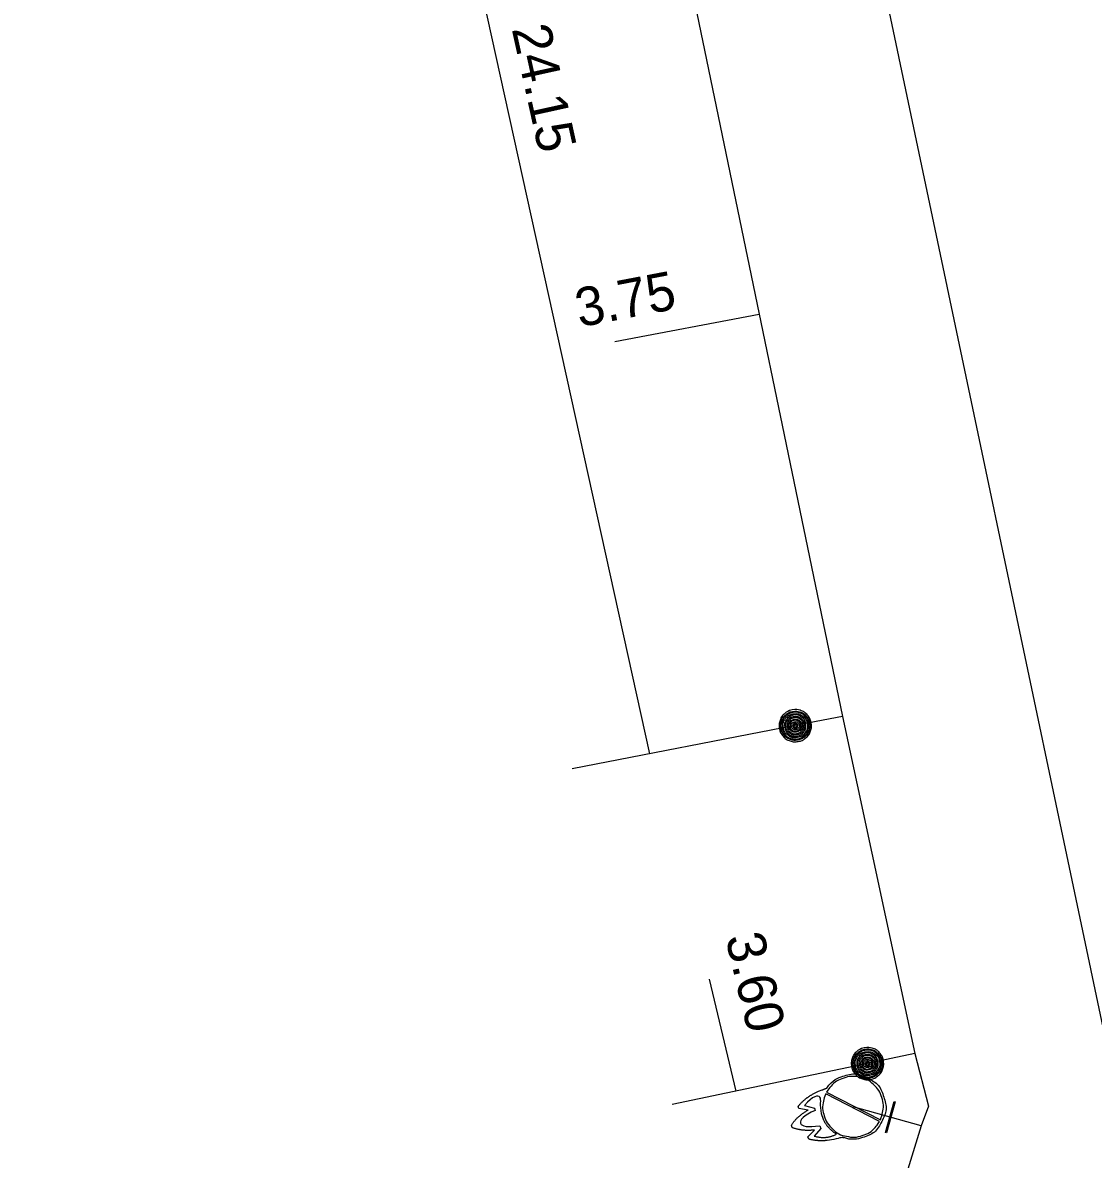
# Model space of a CAD drawing. Extents: x -820257 to -819974, y -1070894 to -1070484.
# Drawn here: x -820218.77 to -820185.49, y -1070621.77 to -1070586.44 of the extents above; entities that cross this region are included whole.
import ezdxf

# ---------------------------------------------------------------- set-up
doc = ezdxf.new("R2010")
doc.units = 0
for name, color, linetype in [('Hyd-odbočka', 7, 'Continuous'), ('Hyd-šoupě', 7, 'Continuous'), ('Hydrant', 7, 'Continuous'), ('Oměrka vodovodu', 7, 'Continuous'), ('Oměrka-text', 7, 'Continuous'), ('Přípojka vodovodu', 7, 'Continuous'), ('Přípojkový uzávěr', 7, 'Continuous'), ('Roz-řad', 7, 'Continuous')]:
    doc.layers.add(name, color=color, linetype=linetype)

msp = doc.modelspace()

# ---------------------------------------------------------------- linework, layer by layer
at = {"layer": 'Hyd-odbočka'}
msp.add_line((-820190.84, -1070620.738), (-820192.96, -1070620.142), dxfattribs=at)
at = {"layer": 'Hyd-šoupě'}
msp.add_lwpolyline([(-820191.65, -1070619.991), (-820191.921, -1070620.954), (-820191.951, -1070620.945), (-820191.68, -1070619.982), (-820191.65, -1070619.991)], dxfattribs=at)
at = {"layer": 'Hydrant'}
for points in [[(-820194.218, -1070619.753), (-820194.034, -1070619.661), (-820193.919, -1070619.617)], [(-820192.139, -1070620.599), (-820193.808, -1070619.739)], [(-820193.781, -1070619.685), (-820192.109, -1070620.545)], [(-820194.359, -1070620.247), (-820194.643, -1070620.195), (-820194.665, -1070620.124)], [(-820194.47, -1070620.1), (-820194.162, -1070620.186), (-820194.139, -1070620.257)], [(-820193.88, -1070620.533), (-820193.936, -1070620.358)], [(-820194.853, -1070620.789), (-820194.877, -1070620.712)], [(-820194.339, -1070621.145), (-820194.361, -1070621.076), (-820194.16, -1070620.864)], [(-820193.988, -1070620.729), (-820193.959, -1070620.819), (-820194.165, -1070621.053)], [(-820193.56, -1070621.156), (-820193.761, -1070621.188)], [(-820193.293, -1070621.087), (-820193.255, -1070621.108)]]:
    msp.add_lwpolyline(points, dxfattribs=at)
for points, degree in [([(-820193.777, -1070619.563), (-820193.59, -1070619.294), (-820193.262, -1070619.189), (-820192.868, -1070619.063), (-820192.501, -1070619.253), (-820192.133, -1070619.443), (-820192.007, -1070619.839), (-820191.881, -1070620.232), (-820192.07, -1070620.6), (-820192.259, -1070620.968), (-820192.653, -1070621.094), (-820192.984, -1070621.2), (-820193.293, -1070621.087)], 3), ([(-820192.109, -1070620.545), (-820192.064, -1070620.448), (-820192.044, -1070620.339), (-820191.992, -1070620.089), (-820192.067, -1070619.856), (-820192.141, -1070619.624), (-820192.327, -1070619.449), (-820192.514, -1070619.273), (-820192.763, -1070619.224), (-820193.013, -1070619.175), (-820193.245, -1070619.249), (-820193.48, -1070619.324), (-820193.655, -1070619.513), (-820193.729, -1070619.595), (-820193.781, -1070619.685)], 3), ([(-820194.665, -1070620.124), (-820194.461, -1070619.884), (-820194.218, -1070619.753)], 2), ([(-820193.936, -1070620.358), (-820194, -1070620.083), (-820193.873, -1070619.747), (-820194.212, -1070619.796), (-820194.47, -1070620.1)], 3), ([(-820193.919, -1070619.617), (-820193.898, -1070619.608), (-820193.777, -1070619.563)], 2), ([(-820193.808, -1070619.739), (-820193.856, -1070619.84), (-820193.878, -1070619.952), (-820193.925, -1070620.203), (-820193.853, -1070620.428), (-820193.781, -1070620.653), (-820193.597, -1070620.83), (-820193.413, -1070621.007), (-820193.161, -1070621.058), (-820192.908, -1070621.11), (-820192.674, -1070621.035), (-820192.441, -1070620.961), (-820192.267, -1070620.774), (-820192.191, -1070620.694), (-820192.139, -1070620.599)], 3), ([(-820194.877, -1070620.712), (-820194.697, -1070620.435), (-820194.359, -1070620.247)], 2), ([(-820194.139, -1070620.257), (-820194.503, -1070620.402), (-820194.742, -1070620.71), (-820194.373, -1070620.793), (-820193.988, -1070620.729)], 3), ([(-820193.477, -1070620.993), (-820193.774, -1070620.794), (-820193.88, -1070620.533)], 2), ([(-820194.16, -1070620.864), (-820194.543, -1070620.909), (-820194.853, -1070620.789)], 2), ([(-820193.761, -1070621.188), (-820194.033, -1070621.224), (-820194.339, -1070621.145)], 2), ([(-820194.165, -1070621.053), (-820193.797, -1070621.16), (-820193.477, -1070620.993)], 2), ([(-820193.255, -1070621.108), (-820193.277, -1070621.099), (-820193.298, -1070621.089), (-820193.453, -1070621.131), (-820193.56, -1070621.156)], 3)]:
    msp.add_open_spline(points, degree=degree, dxfattribs=at)
at = {"layer": 'Oměrka vodovodu'}
for p, q in [((-820199.277, -1070609.167), (-820205.332, -1070581.705)), ((-820200.359, -1070596.356), (-820195.874, -1070595.498)), ((-820196.595, -1070619.655), (-820197.424, -1070616.176))]:
    msp.add_line(p, q, dxfattribs=at)
at = {"layer": 'Přípojka vodovodu'}
for points in [[(-820193.283, -1070608.01), (-820194.756, -1070608.294), (-820201.688, -1070609.632)], [(-820191.043, -1070618.489), (-820192.511, -1070618.797), (-820198.579, -1070620.072)]]:
    msp.add_lwpolyline(points, dxfattribs=at)
at = {"layer": 'Přípojkový uzávěr'}
for points in [[(-820194.851, -1070607.803), (-820194.727, -1070607.78), (-820194.598, -1070607.82), (-820194.468, -1070607.861), (-820194.379, -1070607.966), (-820194.29, -1070608.072), (-820194.265, -1070608.2), (-820194.24, -1070608.328), (-820194.282, -1070608.457), (-820194.325, -1070608.586), (-820194.429, -1070608.673), (-820194.534, -1070608.761), (-820194.662, -1070608.785), (-820194.789, -1070608.81), (-820194.918, -1070608.768), (-820195.048, -1070608.726), (-820195.135, -1070608.621), (-820195.222, -1070608.517), (-820195.247, -1070608.39), (-820195.271, -1070608.261), (-820195.228, -1070608.13), (-820195.185, -1070607.999), (-820195.08, -1070607.913), (-820194.975, -1070607.827), (-820194.851, -1070607.803)], [(-820194.842, -1070607.849), (-820194.954, -1070607.871), (-820195.05, -1070607.949), (-820195.145, -1070608.027), (-820195.184, -1070608.145), (-820195.223, -1070608.264), (-820195.201, -1070608.381), (-820195.178, -1070608.496), (-820195.099, -1070608.591), (-820195.021, -1070608.685), (-820194.903, -1070608.723), (-820194.785, -1070608.762), (-820194.67, -1070608.739), (-820194.554, -1070608.717), (-820194.46, -1070608.638), (-820194.365, -1070608.558), (-820194.327, -1070608.441), (-820194.288, -1070608.324), (-820194.311, -1070608.209), (-820194.333, -1070608.092), (-820194.414, -1070607.997), (-820194.495, -1070607.901), (-820194.613, -1070607.865), (-820194.73, -1070607.828), (-820194.842, -1070607.849)], [(-820194.836, -1070607.883), (-820194.732, -1070607.863), (-820194.623, -1070607.897), (-820194.515, -1070607.931), (-820194.44, -1070608.019), (-820194.365, -1070608.108), (-820194.344, -1070608.215), (-820194.324, -1070608.322), (-820194.359, -1070608.431), (-820194.394, -1070608.539), (-820194.482, -1070608.612), (-820194.57, -1070608.685), (-820194.677, -1070608.706), (-820194.783, -1070608.726), (-820194.892, -1070608.691), (-820195.001, -1070608.656), (-820195.074, -1070608.568), (-820195.146, -1070608.481), (-820195.167, -1070608.374), (-820195.188, -1070608.266), (-820195.152, -1070608.157), (-820195.116, -1070608.047), (-820195.028, -1070607.975), (-820194.939, -1070607.903), (-820194.836, -1070607.883)], [(-820194.828, -1070607.926), (-820194.981, -1070607.956), (-820195.067, -1070608.084), (-820195.153, -1070608.213), (-820195.124, -1070608.366), (-820195.094, -1070608.518), (-820194.966, -1070608.605), (-820194.837, -1070608.692), (-820194.686, -1070608.663), (-820194.532, -1070608.633), (-820194.445, -1070608.505), (-820194.358, -1070608.376), (-820194.388, -1070608.224), (-820194.417, -1070608.071), (-820194.545, -1070607.984), (-820194.673, -1070607.896), (-820194.828, -1070607.926)], [(-820194.819, -1070607.971), (-820194.684, -1070607.945), (-820194.572, -1070608.021), (-820194.461, -1070608.098), (-820194.435, -1070608.231), (-820194.409, -1070608.365), (-820194.485, -1070608.478), (-820194.561, -1070608.59), (-820194.695, -1070608.616), (-820194.829, -1070608.642), (-820194.941, -1070608.566), (-820195.053, -1070608.489), (-820195.079, -1070608.356), (-820195.105, -1070608.222), (-820195.029, -1070608.11), (-820194.953, -1070607.997), (-820194.819, -1070607.971)], [(-820194.812, -1070608.01), (-820194.93, -1070608.033), (-820194.996, -1070608.132), (-820195.063, -1070608.231), (-820195.04, -1070608.348), (-820195.018, -1070608.466), (-820194.919, -1070608.533), (-820194.82, -1070608.6), (-820194.702, -1070608.577), (-820194.585, -1070608.554), (-820194.518, -1070608.455), (-820194.451, -1070608.356), (-820194.474, -1070608.239), (-820194.496, -1070608.121), (-820194.595, -1070608.054), (-820194.693, -1070607.987), (-820194.812, -1070608.01)], [(-820194.804, -1070608.049), (-820194.701, -1070608.029), (-820194.615, -1070608.087), (-820194.53, -1070608.145), (-820194.51, -1070608.247), (-820194.491, -1070608.349), (-820194.549, -1070608.435), (-820194.607, -1070608.52), (-820194.709, -1070608.54), (-820194.81, -1070608.559), (-820194.896, -1070608.502), (-820194.982, -1070608.444), (-820195.001, -1070608.342), (-820195.021, -1070608.24), (-820194.964, -1070608.154), (-820194.906, -1070608.069), (-820194.804, -1070608.049)], [(-820194.795, -1070608.094), (-820194.878, -1070608.11), (-820194.925, -1070608.18), (-820194.972, -1070608.249), (-820194.956, -1070608.332), (-820194.94, -1070608.415), (-820194.87, -1070608.462), (-820194.801, -1070608.509), (-820194.718, -1070608.493), (-820194.635, -1070608.477), (-820194.588, -1070608.408), (-820194.541, -1070608.338), (-820194.557, -1070608.255), (-820194.573, -1070608.172), (-820194.642, -1070608.125), (-820194.712, -1070608.078), (-820194.795, -1070608.094)], [(-820194.788, -1070608.129), (-820194.719, -1070608.115), (-820194.662, -1070608.154), (-820194.604, -1070608.193), (-820194.591, -1070608.262), (-820194.578, -1070608.331), (-820194.617, -1070608.389), (-820194.656, -1070608.446), (-820194.724, -1070608.459), (-820194.793, -1070608.473), (-820194.851, -1070608.434), (-820194.908, -1070608.395), (-820194.922, -1070608.326), (-820194.935, -1070608.257), (-820194.896, -1070608.199), (-820194.857, -1070608.142), (-820194.788, -1070608.129)], [(-820194.78, -1070608.172), (-820194.831, -1070608.181), (-820194.86, -1070608.224), (-820194.888, -1070608.267), (-820194.879, -1070608.318), (-820194.869, -1070608.369), (-820194.826, -1070608.398), (-820194.783, -1070608.427), (-820194.733, -1070608.417), (-820194.681, -1070608.407), (-820194.652, -1070608.364), (-820194.623, -1070608.321), (-820194.633, -1070608.271), (-820194.643, -1070608.22), (-820194.686, -1070608.191), (-820194.728, -1070608.162), (-820194.78, -1070608.172)], [(-820194.771, -1070608.218), (-820194.738, -1070608.211), (-820194.712, -1070608.229), (-820194.686, -1070608.247), (-820194.68, -1070608.28), (-820194.673, -1070608.311), (-820194.691, -1070608.338), (-820194.709, -1070608.365), (-820194.741, -1070608.371), (-820194.773, -1070608.377), (-820194.8, -1070608.359), (-820194.827, -1070608.341), (-820194.833, -1070608.309), (-820194.839, -1070608.277), (-820194.821, -1070608.25), (-820194.803, -1070608.224), (-820194.771, -1070608.218)], [(-820194.765, -1070608.248), (-820194.784, -1070608.252), (-820194.795, -1070608.268), (-820194.806, -1070608.284), (-820194.802, -1070608.303), (-820194.799, -1070608.322), (-820194.783, -1070608.333), (-820194.767, -1070608.344), (-820194.747, -1070608.34), (-820194.728, -1070608.337), (-820194.717, -1070608.321), (-820194.707, -1070608.305), (-820194.71, -1070608.286), (-820194.714, -1070608.266), (-820194.73, -1070608.255), (-820194.746, -1070608.245), (-820194.765, -1070608.248)], [(-820192.614, -1070618.309), (-820192.49, -1070618.283), (-820192.36, -1070618.321), (-820192.23, -1070618.36), (-820192.139, -1070618.464), (-820192.048, -1070618.568), (-820192.021, -1070618.696), (-820191.994, -1070618.823), (-820192.034, -1070618.953), (-820192.074, -1070619.083), (-820192.178, -1070619.172), (-820192.281, -1070619.261), (-820192.408, -1070619.287), (-820192.535, -1070619.314), (-820192.665, -1070619.274), (-820192.795, -1070619.234), (-820192.884, -1070619.131), (-820192.973, -1070619.028), (-820193, -1070618.901), (-820193.027, -1070618.773), (-820192.986, -1070618.642), (-820192.945, -1070618.51), (-820192.841, -1070618.422), (-820192.737, -1070618.335), (-820192.614, -1070618.309)], [(-820192.604, -1070618.355), (-820192.716, -1070618.378), (-820192.81, -1070618.457), (-820192.904, -1070618.537), (-820192.941, -1070618.656), (-820192.978, -1070618.775), (-820192.954, -1070618.892), (-820192.93, -1070619.007), (-820192.849, -1070619.1), (-820192.769, -1070619.193), (-820192.651, -1070619.229), (-820192.532, -1070619.266), (-820192.418, -1070619.241), (-820192.302, -1070619.217), (-820192.209, -1070619.136), (-820192.115, -1070619.056), (-820192.079, -1070618.938), (-820192.043, -1070618.82), (-820192.067, -1070618.705), (-820192.091, -1070618.589), (-820192.174, -1070618.495), (-820192.257, -1070618.401), (-820192.374, -1070618.366), (-820192.492, -1070618.331), (-820192.604, -1070618.355)], [(-820192.597, -1070618.388), (-820192.493, -1070618.366), (-820192.385, -1070618.398), (-820192.276, -1070618.431), (-820192.199, -1070618.518), (-820192.123, -1070618.605), (-820192.1, -1070618.712), (-820192.078, -1070618.819), (-820192.111, -1070618.928), (-820192.145, -1070619.036), (-820192.231, -1070619.111), (-820192.318, -1070619.186), (-820192.425, -1070619.208), (-820192.531, -1070619.23), (-820192.64, -1070619.197), (-820192.75, -1070619.163), (-820192.824, -1070619.077), (-820192.898, -1070618.991), (-820192.92, -1070618.884), (-820192.943, -1070618.777), (-820192.909, -1070618.667), (-820192.874, -1070618.557), (-820192.787, -1070618.483), (-820192.7, -1070618.41), (-820192.597, -1070618.388)], [(-820192.589, -1070618.431), (-820192.741, -1070618.463), (-820192.825, -1070618.593), (-820192.909, -1070618.723), (-820192.877, -1070618.875), (-820192.845, -1070619.027), (-820192.715, -1070619.112), (-820192.585, -1070619.197), (-820192.434, -1070619.165), (-820192.281, -1070619.133), (-820192.196, -1070619.003), (-820192.111, -1070618.873), (-820192.143, -1070618.721), (-820192.175, -1070618.569), (-820192.305, -1070618.484), (-820192.434, -1070618.399), (-820192.589, -1070618.431)], [(-820192.579, -1070618.476), (-820192.445, -1070618.448), (-820192.332, -1070618.522), (-820192.219, -1070618.596), (-820192.191, -1070618.73), (-820192.163, -1070618.863), (-820192.237, -1070618.977), (-820192.311, -1070619.09), (-820192.444, -1070619.118), (-820192.578, -1070619.146), (-820192.691, -1070619.072), (-820192.805, -1070618.998), (-820192.833, -1070618.865), (-820192.861, -1070618.731), (-820192.787, -1070618.618), (-820192.713, -1070618.504), (-820192.579, -1070618.476)], [(-820192.571, -1070618.515), (-820192.688, -1070618.539), (-820192.754, -1070618.639), (-820192.819, -1070618.739), (-820192.794, -1070618.856), (-820192.769, -1070618.974), (-820192.67, -1070619.039), (-820192.57, -1070619.104), (-820192.452, -1070619.08), (-820192.335, -1070619.055), (-820192.27, -1070618.955), (-820192.205, -1070618.855), (-820192.229, -1070618.738), (-820192.254, -1070618.621), (-820192.353, -1070618.555), (-820192.453, -1070618.49), (-820192.571, -1070618.515)], [(-820192.562, -1070618.553), (-820192.46, -1070618.532), (-820192.373, -1070618.588), (-820192.287, -1070618.645), (-820192.266, -1070618.747), (-820192.244, -1070618.848), (-820192.301, -1070618.935), (-820192.358, -1070619.021), (-820192.46, -1070619.043), (-820192.56, -1070619.064), (-820192.647, -1070619.007), (-820192.734, -1070618.951), (-820192.755, -1070618.85), (-820192.776, -1070618.748), (-820192.721, -1070618.661), (-820192.665, -1070618.575), (-820192.562, -1070618.553)], [(-820192.553, -1070618.599), (-820192.635, -1070618.616), (-820192.681, -1070618.686), (-820192.727, -1070618.757), (-820192.71, -1070618.839), (-820192.692, -1070618.922), (-820192.622, -1070618.968), (-820192.552, -1070619.014), (-820192.469, -1070618.996), (-820192.387, -1070618.979), (-820192.341, -1070618.909), (-820192.295, -1070618.838), (-820192.312, -1070618.756), (-820192.33, -1070618.673), (-820192.4, -1070618.627), (-820192.47, -1070618.581), (-820192.553, -1070618.599)], [(-820192.546, -1070618.633), (-820192.477, -1070618.618), (-820192.419, -1070618.656), (-820192.361, -1070618.694), (-820192.346, -1070618.763), (-820192.332, -1070618.832), (-820192.37, -1070618.89), (-820192.408, -1070618.948), (-820192.476, -1070618.962), (-820192.545, -1070618.977), (-820192.603, -1070618.939), (-820192.661, -1070618.901), (-820192.676, -1070618.832), (-820192.69, -1070618.763), (-820192.652, -1070618.705), (-820192.614, -1070618.647), (-820192.546, -1070618.633)], [(-820192.537, -1070618.676), (-820192.587, -1070618.686), (-820192.615, -1070618.73), (-820192.643, -1070618.773), (-820192.633, -1070618.824), (-820192.622, -1070618.874), (-820192.579, -1070618.903), (-820192.535, -1070618.931), (-820192.485, -1070618.92), (-820192.434, -1070618.91), (-820192.406, -1070618.866), (-820192.377, -1070618.823), (-820192.388, -1070618.772), (-820192.399, -1070618.722), (-820192.442, -1070618.693), (-820192.485, -1070618.665), (-820192.537, -1070618.676)], [(-820192.527, -1070618.722), (-820192.495, -1070618.715), (-820192.468, -1070618.732), (-820192.441, -1070618.749), (-820192.434, -1070618.782), (-820192.428, -1070618.813), (-820192.445, -1070618.841), (-820192.462, -1070618.868), (-820192.495, -1070618.874), (-820192.526, -1070618.881), (-820192.554, -1070618.863), (-820192.581, -1070618.846), (-820192.587, -1070618.814), (-820192.594, -1070618.782), (-820192.576, -1070618.755), (-820192.559, -1070618.728), (-820192.527, -1070618.722)], [(-820192.521, -1070618.752), (-820192.54, -1070618.756), (-820192.55, -1070618.772), (-820192.561, -1070618.788), (-820192.557, -1070618.808), (-820192.553, -1070618.827), (-820192.537, -1070618.837), (-820192.52, -1070618.848), (-820192.501, -1070618.844), (-820192.482, -1070618.84), (-820192.471, -1070618.824), (-820192.461, -1070618.807), (-820192.465, -1070618.788), (-820192.469, -1070618.769), (-820192.485, -1070618.758), (-820192.501, -1070618.748), (-820192.521, -1070618.752)]]:
    msp.add_open_spline(points, degree=3, dxfattribs=at)
at = {"layer": 'Roz-řad'}
for points in [[(-820192.294, -1070583.934), (-820183.322, -1070626.593), (-820174.41, -1070657.75)], [(-820197.811, -1070586.146), (-820193.283, -1070608.01), (-820191.043, -1070618.489), (-820190.615, -1070620.124), (-820190.84, -1070620.738)], [(-820190.84, -1070620.738), (-820198.53, -1070645.709), (-820201.034, -1070653.842), (-820205.362, -1070667.895), (-820207.714, -1070675.535), (-820211.419, -1070687.296), (-820213.068, -1070692.533), (-820218.767, -1070711.114)]]:
    msp.add_lwpolyline(points, dxfattribs=at)

# ---------------------------------------------------------------- texts
at = {"layer": 'Oměrka-text'}
for s, rotation, p in [('24.15', 282.434, (-820203.572, -1070586.628)), (' 3.75', 10.8301, (-820201.902, -1070595.996)), (' 3.60', 283.4029, (-820197.038, -1070614.443))]:
    msp.add_text(s, height=1.2, rotation=rotation, dxfattribs=at).set_placement(p)

doc.saveas('drawing.dxf')
